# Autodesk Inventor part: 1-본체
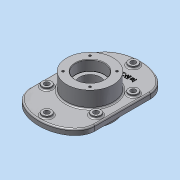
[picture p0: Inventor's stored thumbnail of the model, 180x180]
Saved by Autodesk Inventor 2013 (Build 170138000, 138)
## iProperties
Created: 2015-02
Part Number: 1-본체
Material: 알루미늄 6061
Document SubType Name: Modeling
Designer: dgall
Density: 2.71 g/cm^3
Mass: 1662.1 g
Surface Area: 942.609 cm^2
Volume: 613.321 cm^3
Author: dgall
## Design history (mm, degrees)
sketch "스케치1" dims "d84" = 50, "d85" = 50
  geometry: L1 (-70, 60)-(70, 60); L2 (70, 60)-(70, -60); L3 (70, -60)-(-70, -60); L4 (-70, -60)-(-70, 60); 5 further points; 2 other entities
  constraints: 8 end point, 3 horizontal, 3 midpoint, 2 parallel, 1 coincident, 1 horizontal alignment, 1 perpendicular, 1 vertical alignment, 8 other
  dimensions: "d0" = 120 distance of L3.end L1.start; "d3" = 140 distance between parallel lines of L2 L4
extrude "돌출1" new body sketch "스케치1" distance "d6" = 12; taper "d7" = 0 deg
sketch "스케치2"
  geometry: C1 r 50 at (0, 0); 1 further point
  constraints: 1 centre point, 1 coincident
  dimensions: "d8" = 100 diameter of C1
extrude "돌출2" join sketch "스케치2" distance "d10" = 23; taper "d11" = 0 deg
sketch "스케치3"
  geometry: C1 r 50 at (0, 0) reference; C2 r 31 at (0, 0)
  constraints: 1 centre point, 1 coincident
  dimensions: "d12" = 62 diameter of C2
extrude "돌출3" cut sketch "스케치3" distance "d14" = 22; taper "d15" = 0 deg
sketch "스케치4"
  geometry: C1 r 50 at (0, 0); 1 further point
  constraints: 1 centre point, 1 coincident
  dimensions: "d16" = 100 diameter of C1
extrude "돌출4" join sketch "스케치4" distance "d18" = 35; taper "d19" = 0 deg
sketch "스케치5"
  geometry: C1 r 50 at (0, 0) reference; C2 r 31 at (0, 0)
  constraints: 1 centre point, 1 coincident
  dimensions: "d20" = 62 diameter of C2
extrude "돌출5" cut sketch "스케치5" distance "d22" = 22; taper "d23" = 0 deg
sketch "스케치6"
  geometry: C1 r 50 at (0, 0) reference; C2 r 22.5 at (0, 0)
  constraints: 1 centre point, 1 coincident
  dimensions: "d24" = 45 diameter of C2
extrude "돌출6" cut sketch "스케치6" stored distance "d26" = 22; taper "d27" = 0 deg
chamfer "모따기1" distance "d28" = 1; stored, may be unused: second distance "d29" = 2, angle "d30" = 45 deg
fillet "모깎기1" dims "d31" = 0.3
sketch "스케치7"
  geometry: L1 (0, 0)-(-41, 0); L2 (0, 0)-(-53.009, 53.009); C1 r 32 at (0, 0) reference; C2 r 3 at (-28.991, 28.991); A1 r 41 centre (0, 0) between (-41, 0) and (-28.991, 28.991)
  constraints: 4 end point, 2 centre point, 2 point on circle, 1 coincident, 1 horizontal, 1 point on line
  dimensions: "d33" = 82 diameter of A1; "d36" = 45 deg angle of L2 L1; "d38" = 6 diameter of C2
hole "구멍1" sketch "스케치7" at (-28.991, 28.991) diameter "d39" = 4.917; stored, may be unused: countersink angle "d43" = 90 deg, drill point angle "d45" = 118 deg; dims "d40" = 10, "d41" = 4, "d42" = 2, "d44" = 13
fillet "모깎기3" dims "d49" = 3
node "작업 평면2"
sketch "스케치8"
  geometry: L1 (-70, 60)-(-70, -60) reference; L2 (70, -60)-(70, 60) reference; L3 (-53, -56.976)-(-53, 56.976); L4 (53, 56.976)-(53, -56.976); C1 r 10 at (0, -93); C2 r 10 at (0, 93); C3 r 10 at (53, -39.976); C4 r 10 at (53, 39.976); C5 r 10 at (-53, 39.976); C6 r 10 at (-53, -39.976); A1 r 74 centre (0, -36) between (-70, -60) and (70, -60) reference; A2 r 74 centre (0, 36) between (70, 60) and (-70, 60) reference; A3 r 57 centre (0, 36) between (53, 56.976) and (-53, 56.976); A4 r 57 centre (0, -36) between (-53, -56.976) and (53, -56.976)
  constraints: 8 centre point, 6 point on circle, 4 end point, 4 point on line, 3 equal radius, 1 vertical alignment, 3 other
  dimensions: "d50" = 17 distance between parallel lines of L1 L3; "d51" = 20 diameter of C1; "d52" = 20 diameter of C2; "d54" = 20 diameter of C3; "d55" = 17 distance of L4.end C3.centre; "d56" = 17 distance of L4.start C4.centre; "d57" = 17 distance of L3.end C5.centre; "d58" = 17 distance of L3.start C6.centre
extrude "돌출7" join sketch "스케치8" distance "d59" = 5; taper "d60" = 0 deg
fillet "모깎기4" dims "d61" = 3
fillet "모깎기5" dims "d62" = 3
sketch "스케치9"
  geometry: C1 r 10 at (0, 0) reference; C2 r 5.5 at (0, 0); 1 further point
  constraints: 1 centre point, 1 coincident
  dimensions: "d63" = 11 diameter of C2
extrude "돌출8" cut sketch "스케치9" stored distance "d65" = 5; taper "d66" = 0 deg
sketch "스케치10"
  geometry: C1 r 10 at (0, 0) reference; C2 r 5.5 at (0, 0); 1 further point
  constraints: 1 centre point, 1 coincident
  dimensions: "d67" = 11 diameter of C2
extrude "돌출9" cut sketch "스케치10" stored distance "d69" = 5; taper "d70" = 0 deg
sketch "스케치11"
  geometry: C1 r 10 at (0, 0) reference; C2 r 5.5 at (0, 0); C3 r 10 at (106, 0) reference; C4 r 5.5 at (106, 0); 1 further point
  constraints: 2 centre point, 2 coincident, 1 equal radius
  dimensions: "d77" = 11 diameter of C2
extrude "돌출10" cut sketch "스케치11" stored distance "d79" = 5; taper "d80" = 0 deg
sketch "스케치12"
  geometry: C1 r 53 at (0, 0) reference; A1 r 71 centre (0, 36) between (67, 59.495) and (-67, 59.495) reference; 1 further point
  constraints: 1 vertical alignment, 1 other
  dimensions: "d81" = 65 distance of C1.centre point (0, 65)
feature "엠보싱1" sketch "스케치12" dims "d0" = 120, "d3" = 140, "d18" = 35, "d82" = 1, "d83" = 0, "d84" = 50, "d85" = 50
node "솔리드1"
pattern_circular "원형 패턴1" dims angle "d47" = 360 deg
mirror "대칭1"
pattern_circular "원형 패턴2" dims angle "d72" = 360 deg
pattern_linear "직사각형 패턴1" dims "d76" = 106
